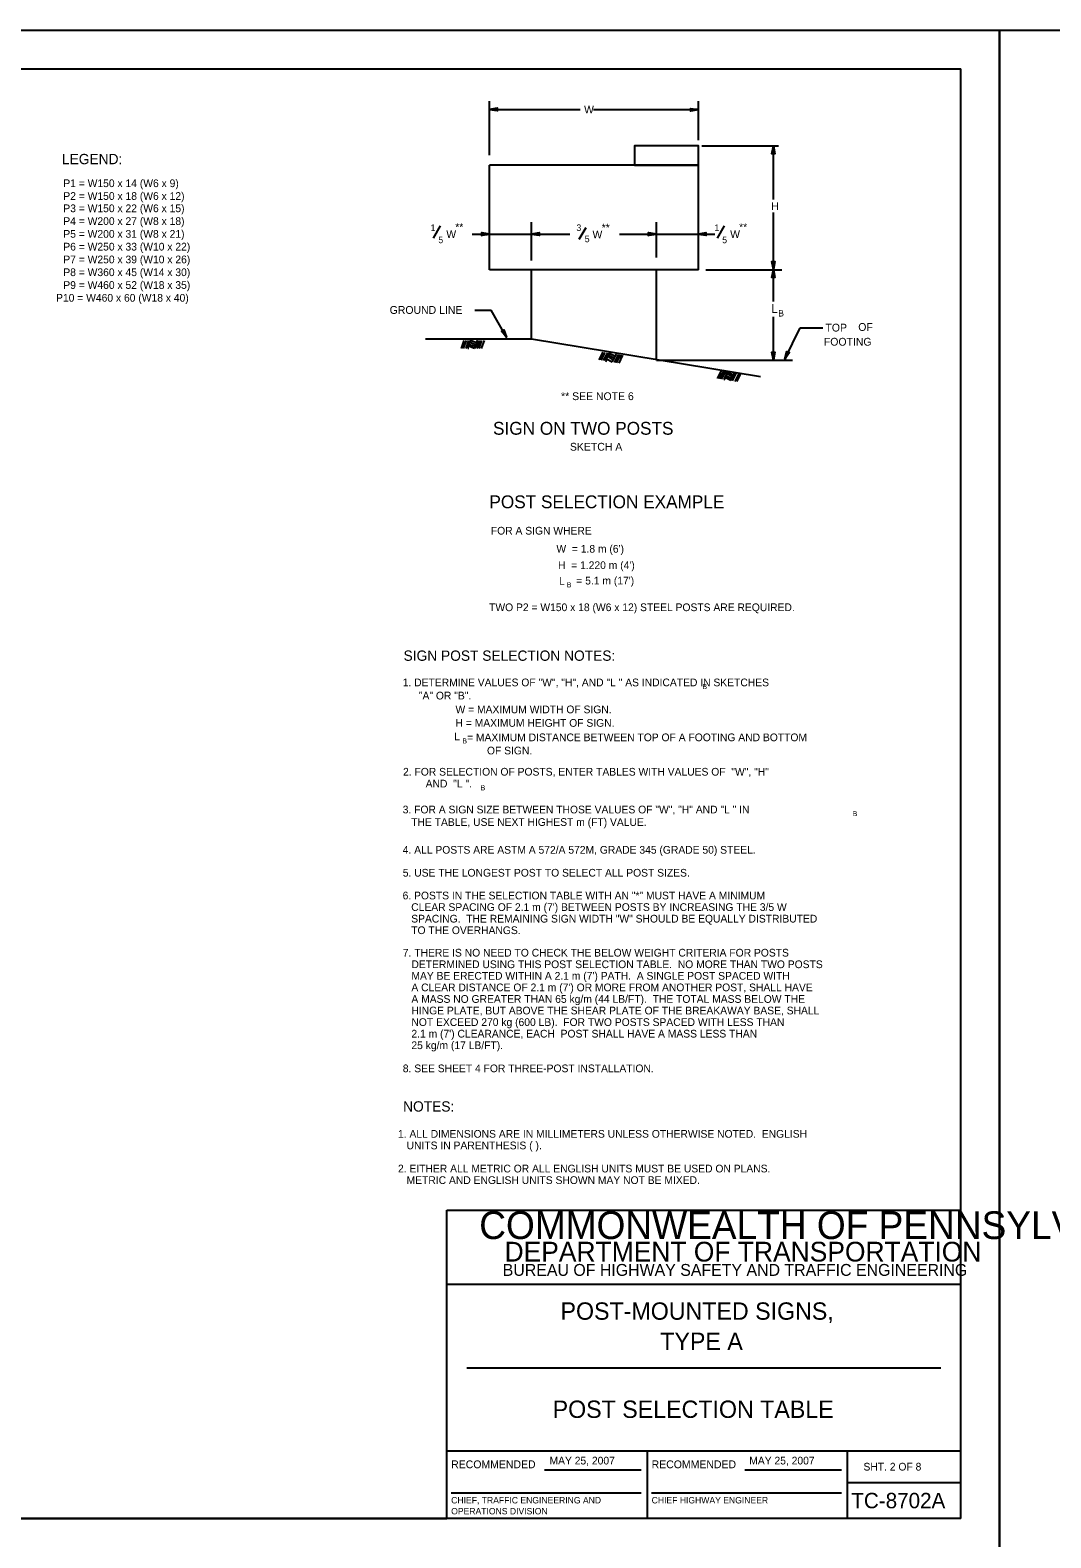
# Model space of a CAD drawing. Extents: x 637580 to 641008, y 294594 to 295782.
# Drawn here: x 638885 to 639282, y 295195 to 295782 of the extents above; entities that cross this region are included whole.
import ezdxf

# ---------------------------------------------------------------- set-up
doc = ezdxf.new("R2010")
doc.units = 0
for name, color, linetype in [('1', 7, 'Continuous'), ('2', 7, 'Continuous'), ('PLT-BNDY', 7, 'Continuous')]:
    doc.layers.add(name, color=color, linetype=linetype)

msp = doc.modelspace()

# ---------------------------------------------------------------- linework, layer by layer
at = {"layer": '1'}
for p, q in [((638461.31, 295766.63), (639247.31, 295766.63)), ((639247.31, 295202.63), (639247.31, 295766.63)), ((639063.94, 295733.01), (639063.94, 295754.01)), ((639063.94, 295750.76), (639099.19, 295750.76)), ((639104.32, 295750.76), (639145.19, 295750.76)), ((639145.19, 295738.89), (639145.19, 295754.01)), ((639146.56, 295736.64), (639176.38, 295736.64)), ((639174.38, 295715.81), (639174.38, 295736.64)), ((639063.94, 295688.39), (639063.94, 295729.14)), ((639145.19, 295729.14), (639063.94, 295729.14)), ((639145.19, 295688.39), (639145.19, 295729.14)), ((639174.38, 295688.39), (639174.38, 295710.68)), ((639042.11, 295700.76), (639044.86, 295705.51)), ((639057.19, 295702.26), (639063.94, 295702.26)), ((639063.94, 295702.26), (639080.19, 295702.26)), ((639080.19, 295692.01), (639080.19, 295706.89)), ((639080.19, 295702.26), (639095.17, 295702.26)), ((639098.83, 295700.26), (639101.46, 295704.89)), ((639114.48, 295702.26), (639128.94, 295702.26)), ((639128.94, 295693.14), (639128.94, 295706.89)), ((639128.94, 295702.26), (639145.19, 295702.26)), ((639145.19, 295702.26), (639151.56, 295702.26)), ((639152.56, 295700.76), (639155.31, 295705.51)), ((639145.19, 295688.39), (639063.94, 295688.39)), ((639080.19, 295661.14), (639080.19, 295688.39)), ((639128.94, 295653.26), (639128.94, 295688.39)), ((639148.06, 295688.39), (639177.63, 295688.39)), ((639174.38, 295676.01), (639174.38, 295688.39)), ((639058.19, 295672.64), (639064.56, 295672.64)), ((639070.56, 295662.14), (639064.56, 295672.64)), ((639174.38, 295653.26), (639174.38, 295670.14)), ((639080.19, 295661.39), (639038.94, 295661.39)), ((639053.94, 295660.89), (639052.94, 295657.76)), ((639054.81, 295660.89), (639053.69, 295657.76)), ((639055.69, 295660.89), (639054.69, 295657.76)), ((639056.44, 295660.89), (639055.31, 295657.76)), ((639058.94, 295660.01), (639056.44, 295660.89)), ((639059.19, 295660.89), (639058.06, 295657.76)), ((639059.19, 295660.76), (639058.81, 295660.89)), ((639060.06, 295660.89), (639058.94, 295657.76)), ((639060.81, 295660.89), (639059.69, 295657.76)), ((639061.81, 295660.89), (639060.69, 295657.76)), ((639169.31, 295646.76), (639080.19, 295661.39)), ((639178.75, 295653.64), (639184.75, 295665.89)), ((639184.75, 295665.89), (639193.63, 295665.89)), ((639055.81, 295657.76), (639055.44, 295657.76)), ((639058.06, 295657.76), (639055.69, 295658.64)), ((639058.31, 295658.51), (639056.06, 295659.26)), ((639058.56, 295659.26), (639056.19, 295660.14)), ((639106.56, 295653.39), (639108.19, 295656.39)), ((639107.31, 295653.26), (639108.94, 295656.26)), ((639108.31, 295653.14), (639109.94, 295656.14)), ((639109.06, 295653.01), (639110.69, 295656.14)), ((639110.19, 295655.26), (639112.56, 295654.01)), ((639110.56, 295656.01), (639112.94, 295654.76)), ((639111.69, 295652.64), (639113.31, 295655.64)), ((639112.56, 295652.39), (639114.19, 295655.39)), ((639112.94, 295655.64), (639113.19, 295655.39)), ((639113.31, 295652.26), (639114.94, 295655.26)), ((639114.31, 295652.14), (639115.81, 295655.14)), ((639109.06, 295653.14), (639109.56, 295652.89)), ((639109.44, 295653.76), (639111.69, 295652.64)), ((639109.94, 295654.64), (639112.06, 295653.26)), ((639128.94, 295653.26), (639181.75, 295653.26)), ((639152.56, 295646.14), (639154.19, 295649.14)), ((639153.44, 295646.01), (639155.06, 295649.01)), ((639154.19, 295645.89), (639155.81, 295648.89)), ((639155.19, 295645.76), (639156.69, 295648.76)), ((639155.19, 295645.89), (639155.56, 295645.76)), ((639155.44, 295646.64), (639157.81, 295645.51)), ((639155.81, 295647.26), (639158.19, 295646.14)), ((639156.19, 295648.01), (639158.44, 295646.89)), ((639156.69, 295648.76), (639158.81, 295647.51)), ((639157.69, 295645.39), (639159.31, 295648.39)), ((639158.44, 295645.26), (639160.06, 295648.26)), ((639158.94, 295648.39), (639159.19, 295648.26)), ((639159.44, 295645.01), (639161.06, 295648.01)), ((639160.19, 295644.89), (639161.69, 295647.89)), ((639047.31, 295202.63), (639047.31, 295322.63)), ((639047.31, 295322.63), (639247.31, 295322.63)), ((639247.31, 295293.63), (639047.31, 295293.63)), ((639055.06, 295261.31), (639239.56, 295261.31)), ((639047.31, 295229), (639247.31, 295229)), ((639125.31, 295229), (639125.31, 295202.63)), ((639203.19, 295202.63), (639203.19, 295229)), ((639085.24, 295221.57), (639122.87, 295221.57)), ((639163.24, 295221.57), (639200.87, 295221.57)), ((639203.19, 295216.63), (639247.31, 295216.63)), ((639048.99, 295212.68), (639122.87, 295212.68)), ((639126.99, 295212.68), (639200.87, 295212.68)), ((639247.31, 295202.63), (638461.31, 295202.63)), ((638461.31, 295202.63), (639047.31, 295202.63))]:
    msp.add_line(p, q, dxfattribs=at)
for points in [[(639066.94, 295750.39), (639066.81, 295750.64), (639063.94, 295750.76), (639066.94, 295750.39), (639067.06, 295750.26), (639063.94, 295750.76), (639066.81, 295751.01), (639066.94, 295751.26), (639063.94, 295750.76), (639067.06, 295751.26), (639066.94, 295751.26)], [(639142.19, 295750.89), (639142.31, 295750.76), (639145.19, 295750.76), (639142.19, 295750.89), (639142.06, 295751.14), (639145.19, 295750.76), (639142.31, 295750.51), (639142.19, 295750.26), (639145.19, 295750.76), (639142.06, 295750.14), (639142.19, 295750.26)], [(639173.88, 295733.76), (639174.13, 295733.76), (639174.38, 295736.64), (639173.88, 295733.76), (639173.75, 295733.51), (639174.38, 295736.64), (639174.38, 295733.76), (639174.63, 295733.76), (639174.38, 295736.64), (639174.88, 295733.51), (639174.63, 295733.76)], [(639061.06, 295702.76), (639061.19, 295702.51), (639063.94, 295702.26), (639061.06, 295702.76), (639060.81, 295702.76), (639063.94, 295702.26), (639061.19, 295702.14), (639061.06, 295701.89), (639063.94, 295702.26), (639060.81, 295701.76), (639061.06, 295701.89)], [(639083.19, 295701.89), (639083.06, 295702.14), (639080.19, 295702.26), (639083.19, 295701.89), (639083.31, 295701.76), (639080.19, 295702.26), (639083.06, 295702.51), (639083.19, 295702.76), (639080.19, 295702.26), (639083.31, 295702.76), (639083.19, 295702.76)], [(639125.94, 295702.76), (639125.94, 295702.51), (639128.94, 295702.26), (639125.94, 295702.76), (639125.69, 295702.76), (639128.94, 295702.26), (639125.94, 295702.14), (639125.94, 295701.89), (639128.94, 295702.26), (639125.69, 295701.76), (639125.94, 295701.89)], [(639148.06, 295701.89), (639147.94, 295702.14), (639145.19, 295702.26), (639148.06, 295701.89), (639148.19, 295701.76), (639145.19, 295702.26), (639147.94, 295702.51), (639148.06, 295702.76), (639145.19, 295702.26), (639148.19, 295702.76), (639148.06, 295702.76)], [(639174.63, 295691.39), (639174.5, 295691.39), (639174.38, 295688.51), (639174.63, 295691.39), (639174.88, 295691.64), (639174.38, 295688.51), (639174.13, 295691.39), (639173.88, 295691.39), (639174.38, 295688.51), (639173.75, 295691.64), (639173.88, 295691.39)], [(639173.88, 295685.51), (639174.13, 295685.64), (639174.38, 295688.39), (639173.88, 295685.51), (639173.75, 295685.39), (639174.38, 295688.39), (639174.38, 295685.64), (639174.63, 295685.51), (639174.38, 295688.39), (639174.88, 295685.39), (639174.63, 295685.51)], [(639069.44, 295664.89), (639069.31, 295664.64), (639070.56, 295662.14), (639069.44, 295664.89), (639069.44, 295665.01), (639070.56, 295662.14), (639068.94, 295664.39), (639068.81, 295664.39), (639070.56, 295662.14), (639068.56, 295664.51), (639068.81, 295664.39)], [(639174.63, 295656.26), (639174.5, 295656.26), (639174.38, 295653.26), (639174.63, 295656.26), (639174.88, 295656.39), (639174.38, 295653.26), (639174.13, 295656.26), (639173.88, 295656.26), (639174.38, 295653.26), (639173.75, 295656.39), (639173.88, 295656.26)], [(639180.38, 295656.14), (639180.13, 295656.14), (639178.75, 295653.64), (639180.38, 295656.14), (639180.63, 295656.26), (639178.75, 295653.64), (639179.88, 295656.26), (639179.63, 295656.39), (639178.75, 295653.64), (639179.63, 295656.64), (639179.63, 295656.39)]]:
    msp.add_lwpolyline(points, dxfattribs=at)
msp.add_lwpolyline([(639145.19, 295729.14), (639145.19, 295736.64), (639120.31, 295736.64), (639120.31, 295729.14)], close=True, dxfattribs=at)
at = {"layer": 'PLT-BNDY'}
for points in [[(638421.31, 295781.63), (639262.31, 295781.63), (639262.31, 295187.63), (638421.31, 295187.63)], [(639262.31, 295781.63), (640103.31, 295781.63), (640103.31, 295187.63), (639262.31, 295187.63)]]:
    msp.add_lwpolyline(points, close=True, dxfattribs=at)

# ---------------------------------------------------------------- texts
at = {"layer": '1'}
for s, height, p in [('W', 3.04, (639100.69, 295749.26)), ('LEGEND:', 4.003, (638897.55, 295729.48)), ('P1 = W150 x 14 (W6 x 9)', 3, (638898.08, 295720.57)), ('P2 = W150 x 18 (W6 x 12)', 3, (638898.08, 295715.6)), ('P3 = W150 x 22 (W6 x 15)', 3, (638898.08, 295710.82)), ('H', 3.04, (639173.5, 295711.64)), ('P4 = W200 x 27 (W8 x 18)', 3, (638898.08, 295705.84)), ('P5 = W200 x 31 (W8 x 21)', 3, (638898.08, 295700.87)), ('1', 2.54, (639040.99, 295703.51)), ('W', 3.04, (639047.09, 295700.75)), ('**', 3, (639050.58, 295703.52)), ('3', 2.54, (639097.71, 295703.51)), ('5', 2.54, (639100.96, 295699.14)), ('W', 3.04, (639103.96, 295700.64)), ('**', 3, (639107.57, 295703.35)), ('1', 2.54, (639151.44, 295703.51)), ('W', 3.04, (639157.54, 295700.75)), ('**', 3, (639161.03, 295703.52)), ('P6 = W250 x 33 (W10 x 22)', 3, (638898.08, 295695.9)), ('5', 2.54, (639043.99, 295698.76)), ('5', 2.54, (639154.44, 295698.76)), ('P7 = W250 x 39 (W10 x 26)', 3, (638898.08, 295690.93)), ('P8 = W360 x 45 (W14 x 30)', 3, (638898.08, 295685.95)), ('P9 = W460 x 52 (W18 x 35)', 3, (638898.08, 295680.98)), ('P10 = W460 x 60 (W18 x 40)', 3, (638895.26, 295676.01)), ('GROUND LINE', 3.0442, (639025.06, 295671.26)), ('L', 3.5, (639173.5, 295671.61)), ('B', 2.5, (639176.25, 295670.23)), ('TOP', 3.043, (639194.62, 295664.39)), ('OF', 3.043, (639207.38, 295664.64)), ('FOOTING', 3.044, (639194, 295658.89)), ('** SEE NOTE 6', 3.0427, (639091.76, 295637.71)), ('SKETCH A', 3.043, (639095.21, 295618.04)), ('FOR A SIGN WHERE ', 3, (639064.44, 295585.41)), ("W  = 1.8 m (6')", 3, (639089.94, 295578.37)), ("H  = 1.220 m (4')", 3, (639090.56, 295571.99)), ('L', 3, (639090.94, 295565.91)), ('B', 2, (639093.94, 295564.86)), (" = 5.1 m (17')", 3, (639096.56, 295565.99)), ('TWO P2 = W150 x 18 (W6 x 12) STEEL POSTS ARE REQUIRED.', 3, (639063.74, 295555.62)), ('1. DETERMINE VALUES OF "W", "H", AND "L " AS INDICATED IN SKETCHES', 3, (639030.14, 295526.39)), ('B', 2, (639146.74, 295525.3)), (' "A" OR "B".', 3, (639035.3, 295521.27)), ('W = MAXIMUM WIDTH OF SIGN.', 3, (639050.68, 295515.89)), ('L', 3, (639050.18, 295505.39)), ('H = MAXIMUM HEIGHT OF SIGN.', 3, (639050.68, 295510.64)), (' = MAXIMUM DISTANCE BETWEEN TOP OF A FOOTING AND BOTTOM', 3, (639054.05, 295505.02)), ('B', 2, (639053.3, 295504.14)), ('OF SIGN.', 3, (639062.92, 295499.89)), ('2. FOR SELECTION OF POSTS, ENTER TABLES WITH VALUES OF  "W", "H" ', 3, (639030.26, 295491.64)), ('AND  "L ".', 3, (639039.06, 295487.02)), ('B', 2, (639060.42, 295485.89)), ('3. FOR A SIGN SIZE BETWEEN THOSE VALUES OF "W", "H" AND "L " IN ', 3, (639030.13, 295476.94)), ('   THE TABLE, USE NEXT HIGHEST m (FT) VALUE.', 3, (639030.1, 295472.07)), ('B', 2, (639205.17, 295475.89)), ('4. ALL POSTS ARE ASTM A 572/A 572M, GRADE 345 (GRADE 50) STEEL.', 3, (639030.14, 295461.27)), ('5. USE THE LONGEST POST TO SELECT ALL POST SIZES.', 3, (639030.16, 295452.35)), ('6. POSTS IN THE SELECTION TABLE WITH AN "*" MUST HAVE A MINIMUM', 3, (639030.1, 295443.49)), ("   CLEAR SPACING OF 2.1 m (7') BETWEEN POSTS BY INCREASING THE 3/5 W", 3, (639030.1, 295438.99)), ('   TO THE OVERHANGS.', 3, (639030.1, 295429.99)), ('   SPACING.  THE REMAINING SIGN WIDTH "W" SHOULD BE EQUALLY DISTRIBUTED', 3, (639030.1, 295434.49)), ('7. THERE IS NO NEED TO CHECK THE BELOW WEIGHT CRITERIA FOR POSTS', 3, (639030.17, 295421.25)), ('   DETERMINED USING THIS POST SELECTION TABLE.  NO MORE THAN TWO POSTS', 3, (639030.17, 295416.75)), ("   MAY BE ERECTED WITHIN A 2.1 m (7') PATH.  A SINGLE POST SPACED WITH", 3, (639030.17, 295412.25)), ("   A CLEAR DISTANCE OF 2.1 m (7') OR MORE FROM ANOTHER POST, SHALL HAVE", 3, (639030.17, 295407.75)), ('   A MASS NO GREATER THAN 65 kg/m (44 LB/FT).  THE TOTAL MASS BELOW THE', 3, (639030.17, 295403.25)), ('   HINGE PLATE, BUT ABOVE THE SHEAR PLATE OF THE BREAKAWAY BASE, SHALL', 3, (639030.17, 295398.75)), ('   NOT EXCEED 270 kg (600 LB).  FOR TWO POSTS SPACED WITH LESS THAN', 3, (639030.17, 295394.25)), ("   2.1 m (7') CLEARANCE, EACH  POST SHALL HAVE A MASS LESS THAN", 3, (639030.17, 295389.75)), ('   25 kg/m (17 LB/FT).', 3, (639030.17, 295385.25)), ('8. SEE SHEET 4 FOR THREE-POST INSTALLATION.', 3, (639030.17, 295376.25)), ('COMMONWEALTH OF PENNSYLVANIA', 10.7828, (639059.9, 295311.36)), ('DEPARTMENT OF TRANSPORTATION', 7.6837, (639069.76, 295302.61)), ('BUREAU OF HIGHWAY SAFETY AND TRAFFIC ENGINEERING', 4.6253, (639069.04, 295297.04)), ('POST-MOUNTED SIGNS,', 6.75, (639091.54, 295279.97)), ('TYPE A', 6.75, (639130.35, 295268.22)), ('POST SELECTION TABLE', 6.75, (639088.47, 295241.78)), ('RECOMMENDED', 3.048, (639048.99, 295222.2)), ('RECOMMENDED', 3.048, (639126.99, 295222.2)), ('SHT. 2 OF 8', 3, (639209.4, 295221.31)), ('CHIEF, TRAFFIC ENGINEERING AND', 2.5, (639048.99, 295208.51)), ('CHIEF HIGHWAY ENGINEER', 2.5, (639126.99, 295208.51)), ('TC-8702A', 6, (639204.68, 295206.63)), ('OPERATIONS DIVISION', 2.5, (639048.99, 295204.26))]:
    msp.add_text(s, height=height, dxfattribs=at).set_placement(p)
at = {"layer": '2'}
for s, height, p in [('SIGN ON TWO POSTS', 5, (639065.27, 295624.24)), ('POST SELECTION EXAMPLE', 5, (639063.87, 295595.64)), ('SIGN POST SELECTION NOTES:', 4.003, (639030.46, 295536.3)), ('NOTES:', 4.003, (639030.29, 295360.95)), (' 1. ALL DIMENSIONS ARE IN MILLIMETERS UNLESS OTHERWISE NOTED.  ENGLISH', 3, (639027.18, 295350.78)), ('    UNITS IN PARENTHESIS ( ).', 3, (639027.18, 295346.28)), (' 2. EITHER ALL METRIC OR ALL ENGLISH UNITS MUST BE USED ON PLANS.', 3, (639027.18, 295337.28)), ('    METRIC AND ENGLISH UNITS SHOWN MAY NOT BE MIXED.     ', 3, (639027.18, 295332.78)), ('MAY 25, 2007', 3, (639087.25, 295223.67)), ('MAY 25, 2007', 3, (639164.97, 295223.67))]:
    msp.add_text(s, height=height, dxfattribs=at).set_placement(p)

doc.saveas('drawing.dxf')
